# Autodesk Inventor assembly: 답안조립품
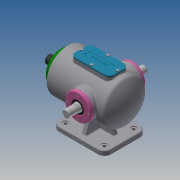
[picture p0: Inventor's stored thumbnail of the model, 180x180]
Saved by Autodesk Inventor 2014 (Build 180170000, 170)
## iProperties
Created: 2021-11
Part Number: 답안조립품
Document SubType Name: Assembly
Designer: kb542
Author: kb542
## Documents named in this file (15)
- C:\Users\kb542\Desktop\711106V1005\답안조립품.iam
- C:\Users\kb542\Desktop\711106V1005\답안본체.ipt.ipt
- C:\Users\kb542\Desktop\711106V1005\베어링 6205.ipt
- 베어링 6205.ipt
- C:\Users\kb542\Desktop\711106V1005\볼트 M4x0.7.ipt
- C:\Users\kb542\Desktop\711106V1005\부시.ipt
- C:\Users\kb542\Desktop\711106V1005\상부커버.ipt
- C:\Users\kb542\Desktop\711106V1005\슬라이드 커버.ipt
- C:\Users\kb542\Desktop\711106V1005\슬라이드.ipt
- C:\Users\kb542\Desktop\711106V1005\오일실.ipt
- 오일실.ipt
- C:\Users\kb542\Desktop\711106V1005\육각머리볼트 M4.ipt
- C:\Users\kb542\Desktop\711106V1005\축 커버.ipt
- C:\Users\kb542\Desktop\711106V1005\편심축.ipt
- 답안본체.ipt
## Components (12 placed, 1 different names)
1. M4x0.7:7
2. M4x0.7:8
3. M4x0.7:12
4. M4x0.7:13
5. M4x0.7:1
6. M4x0.7:3
7. M4x0.7:4
8. M4x0.7:5
9. M4x0.7:2
10. M4x0.7:9
11. M4x0.7:10
12. M4x0.7:11
